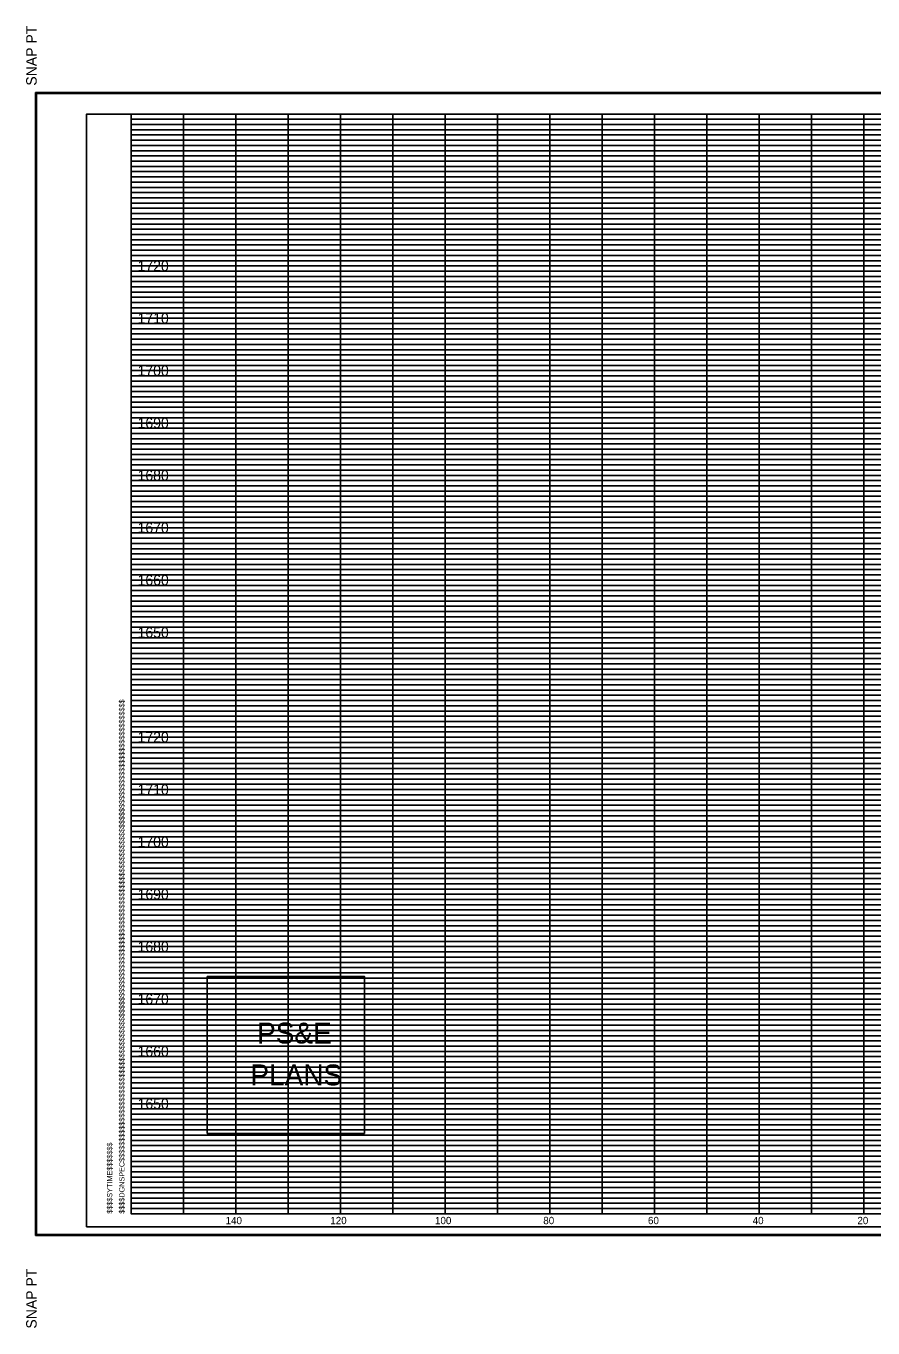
# Model space of a CAD drawing. Extents: x 980 to 1324, y 978 to 1497.
# Drawn here: x 979.9 to 1141.7, y 978.2 to 1226.8 of the extents above; entities that cross this region are included whole.
import ezdxf

# ---------------------------------------------------------------- set-up
doc = ezdxf.new("R2010")
doc.units = 0
for name, color, linetype in [('DESIGN - SHEET - Corner Text', 7, 'Continuous'), ('DESIGN - SHEET - Light Grid', 7, 'Continuous'), ('DESIGN - SHEET - Linework', 7, 'Continuous'), ('DESIGN - SHEET - Plot Shape', 7, 'Continuous'), ('DESIGN - TYPICAL - Finished Grade and Subgrade', 7, 'Continuous')]:
    doc.layers.add(name, color=color, linetype=linetype)

# ---------------------------------------------------------------- blocks, each defined once
blk = doc.blocks.new('XSTSHT')
at = {"layer": 'DESIGN - SHEET - Light Grid'}
for p, q in [((0, 20.9), (8, 20.9)), ((8, 20.9), (16, 20.9)), ((0, 20.8), (8, 20.8)), ((0, 20.7), (8, 20.7)), ((8, 20.8), (16, 20.8)), ((8, 20.7), (16, 20.7)), ((0, 20.6), (8, 20.6)), ((0, 20.5), (8, 20.5)), ((0, 20.4), (8, 20.4)), ((8, 20.6), (16, 20.6)), ((8, 20.5), (16, 20.5)), ((8, 20.4), (16, 20.4)), ((0, 20.3), (8, 20.3)), ((0, 20.2), (8, 20.2)), ((8, 20.3), (16, 20.3)), ((8, 20.2), (16, 20.2)), ((0, 20.1), (8, 20.1)), ((0, 19.9), (8, 19.9)), ((8, 20.1), (16, 20.1)), ((8, 19.9), (16, 19.9)), ((0, 19.8), (8, 19.8)), ((0, 19.7), (8, 19.7)), ((8, 19.8), (16, 19.8)), ((8, 19.7), (16, 19.7)), ((0, 19.6), (8, 19.6)), ((0, 19.5), (8, 19.5)), ((0, 19.4), (8, 19.4)), ((8, 19.6), (16, 19.6)), ((8, 19.5), (16, 19.5)), ((8, 19.4), (16, 19.4)), ((0, 19.3), (8, 19.3)), ((0, 19.2), (8, 19.2)), ((8, 19.3), (16, 19.3)), ((8, 19.2), (16, 19.2)), ((0, 19.1), (8, 19.1)), ((0, 18.9), (8, 18.9)), ((8, 19.1), (16, 19.1)), ((8, 18.9), (16, 18.9)), ((0, 18.8), (8, 18.8)), ((0, 18.7), (8, 18.7)), ((8, 18.8), (16, 18.8)), ((8, 18.7), (16, 18.7)), ((0, 18.6), (8, 18.6)), ((0, 18.5), (8, 18.5)), ((0, 18.4), (8, 18.4)), ((8, 18.6), (16, 18.6)), ((8, 18.5), (16, 18.5)), ((8, 18.4), (16, 18.4)), ((0, 18.3), (8, 18.3)), ((0, 18.2), (8, 18.2)), ((8, 18.3), (16, 18.3)), ((8, 18.2), (16, 18.2)), ((0, 18.1), (8, 18.1)), ((8, 18.1), (16, 18.1)), ((0, 17.9), (8, 17.9)), ((0, 17.8), (8, 17.8)), ((0, 17.7), (8, 17.7)), ((8, 17.9), (16, 17.9)), ((8, 17.8), (16, 17.8)), ((8, 17.7), (16, 17.7)), ((0, 17.6), (8, 17.6)), ((0, 17.5), (8, 17.5)), ((8, 17.6), (16, 17.6)), ((8, 17.5), (16, 17.5)), ((0, 17.4), (8, 17.4)), ((0, 17.3), (8, 17.3)), ((0, 17.2), (8, 17.2)), ((8, 17.4), (16, 17.4)), ((8, 17.3), (16, 17.3)), ((8, 17.2), (16, 17.2)), ((0, 17.1), (8, 17.1)), ((8, 17.1), (16, 17.1)), ((0, 16.9), (8, 16.9)), ((0, 16.8), (8, 16.8)), ((0, 16.7), (8, 16.7)), ((8, 16.9), (16, 16.9)), ((8, 16.8), (16, 16.8)), ((8, 16.7), (16, 16.7)), ((0, 16.6), (8, 16.6)), ((0, 16.5), (8, 16.5)), ((8, 16.6), (16, 16.6)), ((8, 16.5), (16, 16.5)), ((0, 16.4), (8, 16.4)), ((0, 16.3), (8, 16.3)), ((0, 16.2), (8, 16.2)), ((8, 16.4), (16, 16.4)), ((8, 16.3), (16, 16.3)), ((8, 16.2), (16, 16.2)), ((0, 16.1), (8, 16.1)), ((8, 16.1), (16, 16.1)), ((0, 15.9), (8, 15.9)), ((0, 15.8), (8, 15.8)), ((0, 15.7), (8, 15.7)), ((8, 15.9), (16, 15.9)), ((8, 15.8), (16, 15.8)), ((8, 15.7), (16, 15.7)), ((0, 15.6), (8, 15.6)), ((0, 15.5), (8, 15.5)), ((8, 15.6), (16, 15.6)), ((8, 15.5), (16, 15.5)), ((0, 15.4), (8, 15.4)), ((0, 15.3), (8, 15.3)), ((0, 15.2), (8, 15.2)), ((8, 15.4), (16, 15.4)), ((8, 15.3), (16, 15.3)), ((8, 15.2), (16, 15.2)), ((0, 15.1), (8, 15.1)), ((8, 15.1), (16, 15.1)), ((0, 14.9), (8, 14.9)), ((0, 14.8), (8, 14.8)), ((0, 14.7), (8, 14.7)), ((8, 14.9), (16, 14.9)), ((8, 14.8), (16, 14.8)), ((8, 14.7), (16, 14.7)), ((0, 14.6), (8, 14.6)), ((0, 14.5), (8, 14.5)), ((8, 14.6), (16, 14.6)), ((8, 14.5), (16, 14.5)), ((0, 14.4), (8, 14.4)), ((0, 14.3), (8, 14.3)), ((0, 14.2), (8, 14.2)), ((8, 14.4), (16, 14.4)), ((8, 14.3), (16, 14.3)), ((8, 14.2), (16, 14.2)), ((0, 14.1), (8, 14.1)), ((8, 14.1), (16, 14.1)), ((0, 13.9), (8, 13.9)), ((0, 13.8), (8, 13.8)), ((0, 13.7), (8, 13.7)), ((8, 13.9), (16, 13.9)), ((8, 13.8), (16, 13.8)), ((8, 13.7), (16, 13.7)), ((0, 13.6), (8, 13.6)), ((0, 13.5), (8, 13.5)), ((8, 13.6), (16, 13.6)), ((8, 13.5), (16, 13.5)), ((0, 13.4), (8, 13.4)), ((0, 13.3), (8, 13.3)), ((0, 13.2), (8, 13.2)), ((8, 13.4), (16, 13.4)), ((8, 13.3), (16, 13.3)), ((8, 13.2), (16, 13.2)), ((0, 13.1), (8, 13.1)), ((8, 13.1), (16, 13.1)), ((0, 12.9), (8, 12.9)), ((0, 12.8), (8, 12.8)), ((0, 12.7), (8, 12.7)), ((8, 12.9), (16, 12.9)), ((8, 12.8), (16, 12.8)), ((8, 12.7), (16, 12.7)), ((0, 12.6), (8, 12.6)), ((0, 12.5), (8, 12.5)), ((8, 12.6), (16, 12.6)), ((8, 12.5), (16, 12.5)), ((0, 12.4), (8, 12.4)), ((0, 12.3), (8, 12.3)), ((0, 12.2), (8, 12.2)), ((8, 12.4), (16, 12.4)), ((8, 12.3), (16, 12.3)), ((8, 12.2), (16, 12.2)), ((0, 12.1), (8, 12.1)), ((8, 12.1), (16, 12.1)), ((0, 11.9), (8, 11.9)), ((0, 11.8), (8, 11.8)), ((0, 11.7), (8, 11.7)), ((8, 11.9), (16, 11.9)), ((8, 11.8), (16, 11.8)), ((8, 11.7), (16, 11.7)), ((0, 11.6), (8, 11.6)), ((0, 11.5), (8, 11.5)), ((8, 11.6), (16, 11.6)), ((8, 11.5), (16, 11.5)), ((0, 11.4), (8, 11.4)), ((0, 11.3), (8, 11.3)), ((0, 11.2), (8, 11.2)), ((8, 11.4), (16, 11.4)), ((8, 11.3), (16, 11.3)), ((8, 11.2), (16, 11.2)), ((0, 11.1), (8, 11.1)), ((8, 11.1), (16, 11.1)), ((0, 10.9), (8, 10.9)), ((0, 10.8), (8, 10.8)), ((0, 10.7), (8, 10.7)), ((8, 10.9), (16, 10.9)), ((8, 10.8), (16, 10.8)), ((8, 10.7), (16, 10.7)), ((0, 10.6), (8, 10.6)), ((0, 10.5), (8, 10.5)), ((8, 10.6), (16, 10.6)), ((8, 10.5), (16, 10.5)), ((0, 10.4), (8, 10.4)), ((0, 10.3), (8, 10.3)), ((0, 10.2), (8, 10.2)), ((8, 10.4), (16, 10.4)), ((8, 10.3), (16, 10.3)), ((8, 10.2), (16, 10.2)), ((0, 10.1), (8, 10.1)), ((8, 10.1), (16, 10.1)), ((0, 9.9), (8, 9.9)), ((0, 9.8), (8, 9.8)), ((0, 9.7), (8, 9.7)), ((8, 9.9), (16, 9.9)), ((8, 9.8), (16, 9.8)), ((8, 9.7), (16, 9.7)), ((0, 9.6), (8, 9.6)), ((0, 9.5), (8, 9.5)), ((8, 9.6), (16, 9.6)), ((8, 9.5), (16, 9.5)), ((0, 9.4), (8, 9.4)), ((0, 9.3), (8, 9.3)), ((0, 9.2), (8, 9.2)), ((8, 9.4), (16, 9.4)), ((8, 9.3), (16, 9.3)), ((8, 9.2), (16, 9.2)), ((0, 9.1), (8, 9.1)), ((8, 9.1), (16, 9.1)), ((0, 8.9), (8, 8.9)), ((0, 8.8), (8, 8.8)), ((8, 8.9), (16, 8.9)), ((8, 8.8), (16, 8.8)), ((0, 8.7), (8, 8.7)), ((0, 8.6), (8, 8.6)), ((0, 8.5), (8, 8.5)), ((8, 8.7), (16, 8.7)), ((8, 8.6), (16, 8.6)), ((8, 8.5), (16, 8.5)), ((0, 8.4), (8, 8.4)), ((0, 8.3), (8, 8.3)), ((8, 8.4), (16, 8.4)), ((8, 8.3), (16, 8.3)), ((0, 8.2), (8, 8.2)), ((0, 8.1), (8, 8.1)), ((8, 8.2), (16, 8.2)), ((8, 8.1), (16, 8.1)), ((0, 7.9), (8, 7.9)), ((0, 7.8), (8, 7.8)), ((8, 7.9), (16, 7.9)), ((8, 7.8), (16, 7.8)), ((0, 7.7), (8, 7.7)), ((0, 7.6), (8, 7.6)), ((0, 7.5), (8, 7.5)), ((8, 7.7), (16, 7.7)), ((8, 7.6), (16, 7.6)), ((8, 7.5), (16, 7.5)), ((0, 7.4), (8, 7.4)), ((0, 7.3), (8, 7.3)), ((8, 7.4), (16, 7.4)), ((8, 7.3), (16, 7.3)), ((0, 7.2), (8, 7.2)), ((0, 7.1), (8, 7.1)), ((8, 7.2), (16, 7.2)), ((8, 7.1), (16, 7.1)), ((0, 6.9), (8, 6.9)), ((0, 6.8), (8, 6.8)), ((8, 6.9), (16, 6.9)), ((8, 6.8), (16, 6.8)), ((0, 6.7), (8, 6.7)), ((0, 6.6), (8, 6.6)), ((0, 6.5), (8, 6.5)), ((8, 6.7), (16, 6.7)), ((8, 6.6), (16, 6.6)), ((8, 6.5), (16, 6.5)), ((0, 6.4), (8, 6.4)), ((0, 6.3), (8, 6.3)), ((8, 6.4), (16, 6.4)), ((8, 6.3), (16, 6.3)), ((0, 6.2), (8, 6.2)), ((0, 6.1), (8, 6.1)), ((8, 6.2), (16, 6.2)), ((8, 6.1), (16, 6.1)), ((0, 5.9), (8, 5.9)), ((0, 5.8), (8, 5.8)), ((8, 5.9), (16, 5.9)), ((8, 5.8), (16, 5.8)), ((0, 5.7), (8, 5.7)), ((0, 5.6), (8, 5.6)), ((0, 5.5), (8, 5.5)), ((8, 5.7), (16, 5.7)), ((8, 5.6), (16, 5.6)), ((8, 5.5), (16, 5.5)), ((0, 5.4), (8, 5.4)), ((0, 5.3), (8, 5.3)), ((8, 5.4), (16, 5.4)), ((8, 5.3), (16, 5.3)), ((0, 5.2), (8, 5.2)), ((0, 5.1), (8, 5.1)), ((8, 5.2), (16, 5.2)), ((8, 5.1), (16, 5.1)), ((0, 4.9), (8, 4.9)), ((0, 4.8), (8, 4.8)), ((8, 4.9), (16, 4.9)), ((8, 4.8), (16, 4.8)), ((0, 4.7), (8, 4.7)), ((0, 4.6), (8, 4.6)), ((0, 4.5), (8, 4.5)), ((8, 4.7), (16, 4.7)), ((8, 4.6), (16, 4.6)), ((8, 4.5), (16, 4.5)), ((0, 4.4), (8, 4.4)), ((0, 4.3), (8, 4.3)), ((8, 4.4), (16, 4.4)), ((8, 4.3), (16, 4.3)), ((0, 4.2), (8, 4.2)), ((0, 4.1), (8, 4.1)), ((8, 4.2), (16, 4.2)), ((8, 4.1), (16, 4.1)), ((0, 3.9), (8, 3.9)), ((0, 3.8), (8, 3.8)), ((8, 3.9), (16, 3.9)), ((8, 3.8), (16, 3.8)), ((0, 3.7), (8, 3.7)), ((0, 3.6), (8, 3.6)), ((0, 3.5), (8, 3.5)), ((8, 3.7), (16, 3.7)), ((8, 3.6), (16, 3.6)), ((8, 3.5), (16, 3.5)), ((0, 3.4), (8, 3.4)), ((0, 3.3), (8, 3.3)), ((8, 3.4), (16, 3.4)), ((8, 3.3), (16, 3.3)), ((0, 3.2), (8, 3.2)), ((0, 3.1), (8, 3.1)), ((8, 3.2), (16, 3.2)), ((8, 3.1), (16, 3.1)), ((0, 2.9), (8, 2.9)), ((0, 2.8), (8, 2.8)), ((8, 2.9), (16, 2.9)), ((8, 2.8), (16, 2.8)), ((0, 2.7), (8, 2.7)), ((0, 2.6), (8, 2.6)), ((0, 2.5), (8, 2.5)), ((8, 2.7), (16, 2.7)), ((8, 2.6), (16, 2.6)), ((8, 2.5), (16, 2.5)), ((0, 2.4), (8, 2.4)), ((0, 2.3), (8, 2.3)), ((8, 2.4), (16, 2.4)), ((8, 2.3), (16, 2.3)), ((0, 2.2), (8, 2.2)), ((0, 2.1), (8, 2.1)), ((8, 2.2), (16, 2.2)), ((8, 2.1), (16, 2.1)), ((0, 1.9), (8, 1.9)), ((0, 1.8), (8, 1.8)), ((8, 1.9), (16, 1.9)), ((8, 1.8), (16, 1.8)), ((0, 1.7), (8, 1.7)), ((0, 1.6), (8, 1.6)), ((0, 1.5), (8, 1.5)), ((8, 1.7), (16, 1.7)), ((8, 1.6), (16, 1.6)), ((8, 1.5), (16, 1.5)), ((0, 1.4), (8, 1.4)), ((0, 1.3), (8, 1.3)), ((8, 1.4), (16, 1.4)), ((8, 1.3), (16, 1.3)), ((0, 1.2), (8, 1.2)), ((0, 1.1), (8, 1.1)), ((8, 1.2), (16, 1.2)), ((8, 1.1), (16, 1.1)), ((0, 0.9), (8, 0.9)), ((0, 0.8), (8, 0.8)), ((8, 0.9), (16, 0.9)), ((8, 0.8), (16, 0.8)), ((0, 0.7), (8, 0.7)), ((0, 0.6), (8, 0.6)), ((0, 0.5), (8, 0.5)), ((8, 0.7), (16, 0.7)), ((8, 0.6), (16, 0.6)), ((8, 0.5), (16, 0.5)), ((0, 0.4), (8, 0.4)), ((0, 0.3), (8, 0.3)), ((8, 0.4), (16, 0.4)), ((8, 0.3), (16, 0.3)), ((0, 0.2), (8, 0.2)), ((0, 0.1), (8, 0.1)), ((8, 0.2), (16, 0.2)), ((8, 0.1), (16, 0.1))]:
    blk.add_line(p, q, dxfattribs=at)
at = {"layer": 'DESIGN - SHEET - Linework'}
for p, q in [((-1.823, -0.414), (-1.823, 21.414)), ((-1.823, 21.414), (32.217, 21.414)), ((1, 0), (1, 21)), ((2, 0), (2, 21)), ((3, 0), (3, 21)), ((4, 0), (4, 21)), ((5, 0), (5, 21)), ((6, 0), (6, 21)), ((7, 0), (7, 21)), ((8, 0), (8, 21)), ((9, 0), (9, 21)), ((10, 0), (10, 21)), ((11, 0), (11, 21)), ((12, 0), (12, 21)), ((13, 0), (13, 21)), ((14, 0), (14, 21)), ((0, 20), (28, 20)), ((0, 19), (32, 19)), ((0, 18), (32, 18)), ((0, 17), (32, 17)), ((0, 16), (32, 16)), ((0, 15), (32, 15)), ((0, 14), (32, 14)), ((0, 13), (32, 13)), ((0, 12), (32, 12)), ((0, 11), (32, 11)), ((0, 10), (32, 10)), ((0, 9), (32, 9)), ((0, 8), (32, 8)), ((0, 7), (32, 7)), ((0, 6), (32, 6)), ((0, 5), (32, 5)), ((0, 4), (32, 4)), ((0, 3), (32, 3)), ((0, 2), (32, 2)), ((0, 1), (32, 1)), ((-1.823, -0.414), (32.217, -0.414))]:
    blk.add_line(p, q, dxfattribs=at)
blk.add_lwpolyline([(0, 21), (0, 0), (32, 0), (32, 21), (0, 21)], dxfattribs=at)
at = {"layer": 'DESIGN - SHEET - Plot Shape'}
for points in [[(-1.803, 21.394), (32.197, 21.394), (32.197, -0.394), (-1.803, -0.394)], [(-0.85, 21), (32, 21), (32, -0.25), (-0.85, -0.25)]]:
    blk.add_lwpolyline(points, close=True, dxfattribs=at)
at = {"layer": 'DESIGN - SHEET - Corner Text'}
for s, height, p in [('  SNAP PT', 0.2, (-1.803, 21.394)), ('$$$$DGNSPEC$$$$$$$$$$$$$$$$$$$$$$$$$$$$$$$$$$$$$$$$$$$$$$$$$$$$$$$$$$$$$$$$$$$$$$$$$$$$$$$$$$$$$$$$$$$$$$$$$$$$$$$$$$$$$$$$$$$', 0.100002, (-0.126, 0)), ('$$$$SYTIME$$$$$$$', 0.1, (-0.358, 0)), ('SNAP PT  ', 0.2, (-1.803, -2.194))]:
    blk.add_text(s, height=height, rotation=90, dxfattribs=at).set_placement(p)

msp = doc.modelspace()

# ---------------------------------------------------------------- linework, layer by layer
at = {"layer": 'DESIGN - SHEET - Corner Text'}
msp.add_lwpolyline([(1014.56, 1045.32), (1014.56, 1015.32), (1044.56, 1015.32), (1044.56, 1045.32)], close=True, dxfattribs=at)
at = {"layer": 'DESIGN - SHEET - Plot Shape'}
msp.add_lwpolyline([(991.5, 997.5), (1320, 997.5), (1320, 1210), (991.5, 1210)], close=True, dxfattribs=at)

# ---------------------------------------------------------------- block references
at = {"layer": 'DESIGN - TYPICAL - Finished Grade and Subgrade', "xscale": 10, "yscale": 10}
msp.add_blockref('XSTSHT', (1000, 1000), dxfattribs=at)

# ---------------------------------------------------------------- texts
at = {"layer": 'DESIGN - SHEET - Corner Text'}
for s, height, p in [('1720', 2, (1001.25, 1180)), ('1710', 2, (1001.25, 1170)), ('1700', 2, (1001.25, 1160)), ('1690', 2, (1001.25, 1150)), ('1680', 2, (1001.25, 1140)), ('1670', 2, (1001.25, 1130)), ('1660', 2, (1001.25, 1120)), ('1650', 2, (1001.25, 1110)), ('1720', 2, (1001.25, 1090)), ('1710', 2, (1001.25, 1080)), ('1700', 2, (1001.25, 1070)), ('1690', 2, (1001.25, 1060)), ('1680', 2, (1001.25, 1050)), ('1670', 2, (1001.25, 1040)), ('PS&E', 4, (1024.07, 1032.5)), ('1660', 2, (1001.25, 1030)), ('PLANS', 4, (1022.79, 1024.5)), ('1650', 2, (1001.25, 1020)), ('140', 1.4, (1018.06, 998)), ('120', 1.4, (1038.06, 998)), ('100', 1.4, (1058.06, 998)), ('80', 1.4, (1078.74, 998)), ('60', 1.4, (1098.74, 998)), ('40', 1.4, (1118.74, 998)), ('20', 1.4, (1138.74, 998))]:
    msp.add_text(s, height=height, dxfattribs=at).set_placement(p)

doc.saveas('drawing.dxf')
